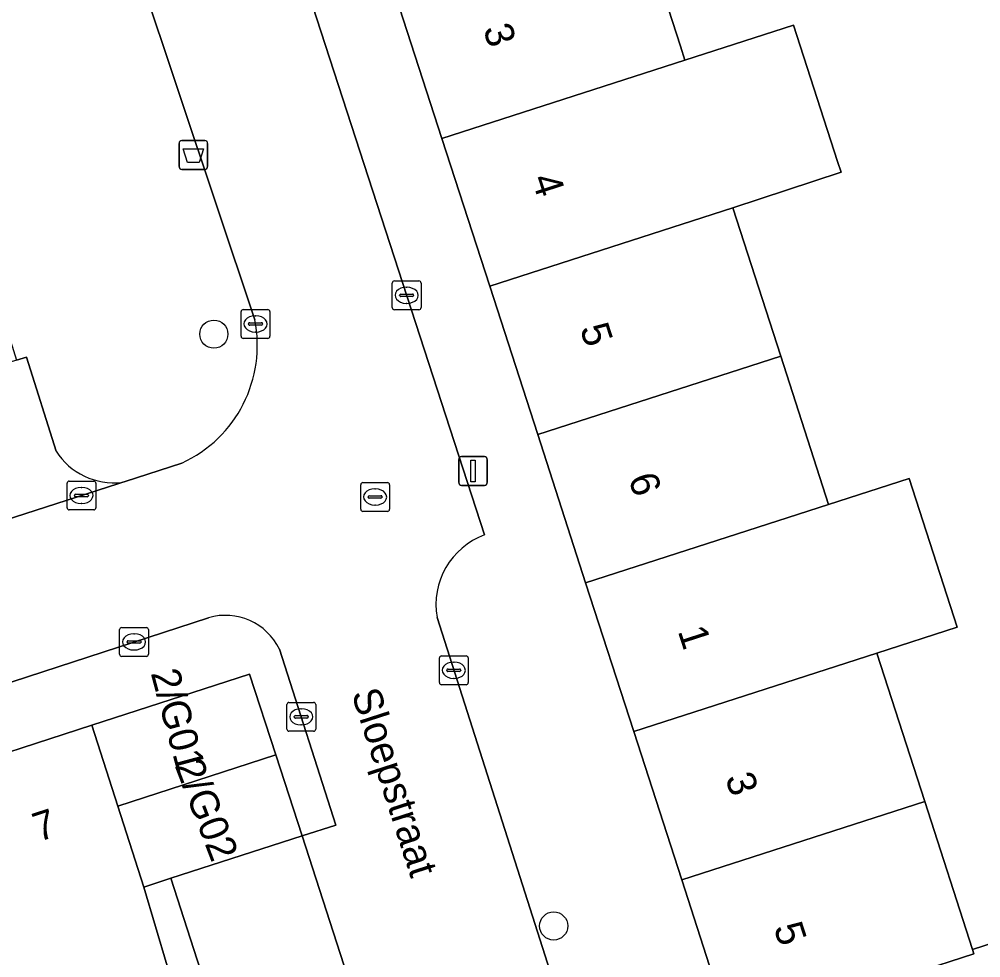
# Model space of a CAD drawing. Extents: x 159371 to 159986, y 382987 to 383597.
# Drawn here: x 159572.4 to 159605.74, y 383099.38 to 383131.92 of the extents above; entities that cross this region are included whole.
import ezdxf

# ---------------------------------------------------------------- set-up
doc = ezdxf.new("R2010")
doc.units = 0
for name, color, linetype in [('IMGEO_Afvalbak', 7, 'Continuous'), ('IMGEO_Boom', 7, 'Continuous'), ('IMGEO_Erf', 7, 'Continuous'), ('IMGEO_Groenvoorziening', 7, 'Continuous'), ('IMGEO_Kolk', 7, 'Continuous'), ('IMGEO_Lichtmast', 7, 'Continuous'), ('IMGEO_Openbare_ruimte_label', 7, 'Continuous'), ('IMGEO_Pand', 7, 'Continuous'), ('IMGEO_Pand_nummerreeks', 7, 'Continuous'), ('IMGEO_Parkeervlak_open', 7, 'Continuous'), ('IMGEO_Rijbaan_lokaal_open', 7, 'Continuous'), ('IMGEO_Rioolput', 7, 'Continuous'), ('IMGEO_Voetpad_open', 7, 'Continuous')]:
    doc.layers.add(name, color=color, linetype=linetype)

msp = doc.modelspace()

# ---------------------------------------------------------------- linework, layer by layer
at = {"layer": 'IMGEO_Afvalbak'}
for p, q in [((159577.943, 383126.815), (159577.943, 383127.615)), ((159577.943, 383127.615), (159577.943, 383126.815)), ((159578.043, 383127.715), (159578.833, 383127.715)), ((159578.833, 383127.715), (159578.043, 383127.715)), ((159578.933, 383127.615), (159578.933, 383126.815)), ((159578.933, 383126.815), (159578.933, 383127.615)), ((159578.833, 383126.715), (159578.043, 383126.715)), ((159578.043, 383126.715), (159578.833, 383126.715))]:
    msp.add_line(p, q, dxfattribs=at)
msp.add_lwpolyline([(159578.086, 383127.429), (159578.79, 383127.429), (159578.641, 383126.959), (159578.235, 383126.959), (159578.086, 383127.429)], dxfattribs=at)
for centre, start, end in [((159578.043, 383127.615), 90, 180), ((159578.043, 383127.615), 90, 180), ((159578.833, 383127.615), 0, 90), ((159578.833, 383127.615), 360, 90), ((159578.043, 383126.815), 180, 270), ((159578.043, 383126.815), 180, 270), ((159578.833, 383126.815), 270, 0), ((159578.833, 383126.815), 270, 0)]:
    msp.add_arc(centre, 0.1, start, end, dxfattribs=at)
at = {"layer": 'IMGEO_Boom'}
for centre in [(159579.15, 383121.002), (159590.933, 383100.481)]:
    msp.add_circle(centre, 0.489, dxfattribs=at)
at = {"layer": 'IMGEO_Erf'}
msp.add_lwpolyline([(159593.791, 383135.74), (159595.329, 383130.983), (159595.484, 383130.504), (159599.251, 383131.718), (159600.775, 383126.99), (159600.896, 383126.615), (159597.141, 383125.381), (159598.804, 383120.238), (159600.467, 383115.094), (159603.258, 383115.994), (159604.92, 383110.841), (159602.134, 383109.942), (159603.797, 383104.799), (159605.459, 383099.66), (159616.414, 383103.202)], dxfattribs=at)
at = {"layer": 'IMGEO_Groenvoorziening'}
for points in [[(159568.059, 383133.514), (159569.251, 383129.752), (159571.294, 383123.299), (159571.459, 383122.778), (159572.307, 383120.099), (159572.649, 383120.207), (159573.679, 383116.948)], [(159580.568, 383121.503), (159576.594, 383133.402)], [(159575.96, 383115.86), (159576.075, 383115.897), (159578.043, 383116.532)]]:
    msp.add_lwpolyline(points, dxfattribs=at)
for centre, radius, start, end in [((159576.16, 383120.615), 4.497, 294.7577, 11.386), ((159575.69, 383118.23), 2.385, 212.5102, 276.489)]:
    msp.add_arc(centre, radius, start, end, dxfattribs=at)
at = {"layer": 'IMGEO_Kolk'}
for p, q in [((159585.334, 383121.923), (159585.334, 383122.775)), ((159585.409, 383122.849), (159586.261, 383122.849)), ((159585.822, 383122.629), (159585.847, 383122.629)), ((159586.335, 383122.775), (159586.335, 383121.923)), ((159585.593, 383122.343), (159585.593, 383122.355)), ((159586.031, 383122.306), (159585.633, 383122.306)), ((159585.636, 383122.392), (159586.034, 383122.392)), ((159586.077, 383122.355), (159586.077, 383122.343)), ((159585.845, 383122.069), (159585.82, 383122.069)), ((159580.093, 383120.93), (159580.093, 383121.782)), ((159580.168, 383121.856), (159581.02, 383121.856)), ((159580.581, 383121.636), (159580.606, 383121.636)), ((159581.094, 383121.782), (159581.094, 383120.93)), ((159586.261, 383121.849), (159585.409, 383121.849)), ((159580.352, 383121.35), (159580.352, 383121.362)), ((159580.79, 383121.313), (159580.392, 383121.313)), ((159580.395, 383121.399), (159580.793, 383121.399)), ((159580.836, 383121.362), (159580.836, 383121.35)), ((159580.604, 383121.076), (159580.579, 383121.076)), ((159581.02, 383120.856), (159580.168, 383120.856)), ((159574.134, 383115.907), (159574.986, 383115.907)), ((159574.059, 383114.981), (159574.059, 383115.833)), ((159574.547, 383115.687), (159574.572, 383115.687)), ((159575.06, 383115.833), (159575.06, 383114.981)), ((159574.318, 383115.401), (159574.318, 383115.413)), ((159574.756, 383115.364), (159574.358, 383115.364)), ((159574.361, 383115.45), (159574.759, 383115.45)), ((159574.802, 383115.413), (159574.802, 383115.401)), ((159574.986, 383114.907), (159574.134, 383114.907)), ((159574.57, 383115.127), (159574.545, 383115.127)), ((159575.883, 383109.904), (159575.883, 383110.756)), ((159575.958, 383110.83), (159576.81, 383110.83)), ((159576.371, 383110.61), (159576.396, 383110.61)), ((159576.884, 383110.756), (159576.884, 383109.904)), ((159576.142, 383110.324), (159576.142, 383110.336)), ((159576.58, 383110.287), (159576.182, 383110.287)), ((159576.185, 383110.373), (159576.583, 383110.373)), ((159576.626, 383110.336), (159576.626, 383110.324)), ((159576.394, 383110.05), (159576.369, 383110.05)), ((159576.81, 383109.83), (159575.958, 383109.83)), ((159586.969, 383108.921), (159586.969, 383109.773)), ((159587.044, 383109.847), (159587.896, 383109.847)), ((159587.457, 383109.627), (159587.482, 383109.627)), ((159587.97, 383109.773), (159587.97, 383108.921)), ((159587.228, 383109.341), (159587.228, 383109.353)), ((159587.666, 383109.304), (159587.268, 383109.304)), ((159587.271, 383109.39), (159587.669, 383109.39)), ((159587.712, 383109.353), (159587.712, 383109.341)), ((159587.48, 383109.067), (159587.455, 383109.067)), ((159587.896, 383108.847), (159587.044, 383108.847)), ((159581.755, 383108.233), (159582.607, 383108.233)), ((159581.68, 383107.307), (159581.68, 383108.159)), ((159582.168, 383108.013), (159582.193, 383108.013)), ((159582.681, 383108.159), (159582.681, 383107.307)), ((159581.939, 383107.727), (159581.939, 383107.739)), ((159582.377, 383107.69), (159581.979, 383107.69)), ((159581.982, 383107.776), (159582.38, 383107.776)), ((159582.423, 383107.739), (159582.423, 383107.727)), ((159582.607, 383107.233), (159581.755, 383107.233)), ((159582.191, 383107.453), (159582.166, 383107.453))]:
    msp.add_line(p, q, dxfattribs=at)
for points in [[(159585.334, 383121.923), (159585.334, 383122.775)], [(159585.409, 383122.849), (159586.261, 383122.849)], [(159586.335, 383122.775), (159586.335, 383121.923)], [(159580.093, 383120.93), (159580.093, 383121.782)], [(159580.168, 383121.856), (159581.02, 383121.856)], [(159581.094, 383121.782), (159581.094, 383120.93)], [(159586.261, 383121.849), (159585.409, 383121.849)], [(159581.02, 383120.856), (159580.168, 383120.856)], [(159574.134, 383115.907), (159574.986, 383115.907)], [(159574.059, 383114.981), (159574.059, 383115.833)], [(159575.06, 383115.833), (159575.06, 383114.981)], [(159574.986, 383114.907), (159574.134, 383114.907)], [(159575.883, 383109.904), (159575.883, 383110.756)], [(159575.958, 383110.83), (159576.81, 383110.83)], [(159576.884, 383110.756), (159576.884, 383109.904)], [(159576.81, 383109.83), (159575.958, 383109.83)], [(159586.969, 383108.921), (159586.969, 383109.773)], [(159587.044, 383109.847), (159587.896, 383109.847)], [(159587.97, 383109.773), (159587.97, 383108.921)], [(159587.896, 383108.847), (159587.044, 383108.847)], [(159581.755, 383108.233), (159582.607, 383108.233)], [(159581.68, 383107.307), (159581.68, 383108.159)], [(159582.681, 383108.159), (159582.681, 383107.307)], [(159582.607, 383107.233), (159581.755, 383107.233)]]:
    msp.add_lwpolyline(points, dxfattribs=at)
for centre, radius, start, end in [((159585.411, 383122.773), 0.0765, 91.552, 178.448), ((159585.411, 383122.773), 0.0765, 91.552, 178.448), ((159586.259, 383122.773), 0.0765, 1.552, 88.448), ((159586.259, 383122.773), 0.0765, 1.552, 88.448), ((159585.633, 383122.352), 0.0403, 85.8775, 175.7526), ((159585.63, 383122.342), 0.0366, 178.938, 274.7102), ((159586.034, 383122.349), 0.043, 264.8664, 352.4533), ((159586.038, 383122.354), 0.0386, 1.7309, 96.639), ((159585.411, 383121.925), 0.0765, 181.552, 268.448), ((159585.411, 383121.925), 0.0765, 181.552, 268.448), ((159586.259, 383121.925), 0.0765, 271.552, 358.448), ((159586.259, 383121.925), 0.0765, 271.552, 358.448), ((159580.17, 383121.78), 0.0765, 91.552, 178.448), ((159580.17, 383121.78), 0.0765, 91.552, 178.448), ((159581.018, 383121.78), 0.0765, 1.552, 88.448), ((159581.018, 383121.78), 0.0765, 1.552, 88.448), ((159580.392, 383121.359), 0.0403, 85.8775, 175.7526), ((159580.389, 383121.349), 0.0366, 178.938, 274.7102), ((159580.793, 383121.356), 0.043, 264.8664, 352.4533), ((159580.797, 383121.361), 0.0386, 1.7309, 96.639), ((159580.17, 383120.932), 0.0765, 181.552, 268.448), ((159580.17, 383120.932), 0.0765, 181.552, 268.448), ((159581.018, 383120.932), 0.0765, 271.552, 358.448), ((159581.018, 383120.932), 0.0765, 271.552, 358.448), ((159574.136, 383115.831), 0.0765, 91.552, 178.448), ((159574.136, 383115.831), 0.0765, 91.552, 178.448), ((159574.984, 383115.831), 0.0765, 1.552, 88.448), ((159574.984, 383115.831), 0.0765, 1.552, 88.448), ((159574.358, 383115.41), 0.0403, 85.8775, 175.7526), ((159574.355, 383115.4), 0.0366, 178.938, 274.7102), ((159574.759, 383115.407), 0.043, 264.8664, 352.4533), ((159574.763, 383115.412), 0.0386, 1.7309, 96.639), ((159574.136, 383114.983), 0.0765, 181.552, 268.448), ((159574.136, 383114.983), 0.0765, 181.552, 268.448), ((159574.984, 383114.983), 0.0765, 271.552, 358.448), ((159574.984, 383114.983), 0.0765, 271.552, 358.448), ((159575.96, 383110.754), 0.0765, 91.552, 178.448), ((159575.96, 383110.754), 0.0765, 91.552, 178.448), ((159576.808, 383110.754), 0.0765, 1.552, 88.448), ((159576.808, 383110.754), 0.0765, 1.552, 88.448), ((159576.182, 383110.333), 0.0403, 85.8775, 175.7526), ((159576.179, 383110.323), 0.0366, 178.938, 274.7102), ((159576.583, 383110.33), 0.043, 264.8664, 352.4533), ((159576.587, 383110.335), 0.0386, 1.7309, 96.639), ((159575.96, 383109.906), 0.0765, 181.552, 268.448), ((159575.96, 383109.906), 0.0765, 181.552, 268.448), ((159576.808, 383109.906), 0.0765, 271.552, 358.448), ((159576.808, 383109.906), 0.0765, 271.552, 358.448), ((159587.046, 383109.771), 0.0765, 91.552, 178.448), ((159587.046, 383109.771), 0.0765, 91.552, 178.448), ((159587.894, 383109.771), 0.0765, 1.552, 88.448), ((159587.894, 383109.771), 0.0765, 1.552, 88.448), ((159587.268, 383109.35), 0.0403, 85.8775, 175.7526), ((159587.265, 383109.34), 0.0366, 178.938, 274.7102), ((159587.669, 383109.347), 0.043, 264.8664, 352.4533), ((159587.673, 383109.352), 0.0386, 1.7309, 96.639), ((159587.046, 383108.923), 0.0765, 181.552, 268.448), ((159587.046, 383108.923), 0.0765, 181.552, 268.448), ((159587.894, 383108.923), 0.0765, 271.552, 358.448), ((159587.894, 383108.923), 0.0765, 271.552, 358.448), ((159581.757, 383108.157), 0.0765, 91.552, 178.448), ((159581.757, 383108.157), 0.0765, 91.552, 178.448), ((159582.605, 383108.157), 0.0765, 1.552, 88.448), ((159582.605, 383108.157), 0.0765, 1.552, 88.448), ((159581.979, 383107.736), 0.0403, 85.8775, 175.7526), ((159581.976, 383107.726), 0.0366, 178.938, 274.7102), ((159582.38, 383107.733), 0.043, 264.8664, 352.4533), ((159582.384, 383107.738), 0.0386, 1.7309, 96.639), ((159581.757, 383107.309), 0.0765, 181.552, 268.448), ((159581.757, 383107.309), 0.0765, 181.552, 268.448), ((159582.605, 383107.309), 0.0765, 271.552, 358.448), ((159582.605, 383107.309), 0.0765, 271.552, 358.448)]:
    msp.add_arc(centre, radius, start, end, dxfattribs=at)
for centre, major_axis, ratio, start_param, end_param in [((159585.821, 383122.349), (-0.387, 0.002), 0.722429, 4.712389, 7.853982), ((159585.846, 383122.349), (-0.39, 0.002), 0.717154, 1.570796, 4.712389), ((159580.58, 383121.356), (-0.387, 0.002), 0.722429, 4.712389, 7.853982), ((159580.605, 383121.356), (-0.39, 0.002), 0.717154, 1.570796, 4.712389), ((159574.546, 383115.407), (-0.387, 0.002), 0.722429, 4.712389, 7.853982), ((159574.571, 383115.407), (-0.39, 0.002), 0.717154, 1.570796, 4.712389), ((159576.37, 383110.33), (-0.387, 0.002), 0.722429, 4.712389, 7.853982), ((159576.395, 383110.33), (-0.39, 0.002), 0.717154, 1.570796, 4.712389), ((159587.456, 383109.347), (-0.387, 0.002), 0.722429, 4.712389, 7.853982), ((159587.481, 383109.347), (-0.39, 0.002), 0.717154, 1.570796, 4.712389), ((159582.167, 383107.733), (-0.387, 0.002), 0.722429, 4.712389, 7.853982), ((159582.192, 383107.733), (-0.39, 0.002), 0.717154, 1.570796, 4.712389)]:
    msp.add_ellipse(centre, major_axis=major_axis, ratio=ratio, start_param=start_param, end_param=end_param, dxfattribs=at)
at = {"layer": 'IMGEO_Lichtmast'}
for p, q in [((159587.642, 383115.857), (159587.642, 383116.657)), ((159587.642, 383116.657), (159587.642, 383115.857)), ((159587.742, 383116.757), (159588.532, 383116.757)), ((159588.532, 383116.757), (159587.742, 383116.757)), ((159588.632, 383116.657), (159588.632, 383115.857)), ((159588.632, 383115.857), (159588.632, 383116.657)), ((159588.532, 383115.757), (159587.742, 383115.757)), ((159587.742, 383115.757), (159588.532, 383115.757))]:
    msp.add_line(p, q, dxfattribs=at)
msp.add_lwpolyline([(159588.062, 383116.632), (159588.212, 383116.632), (159588.212, 383115.882), (159588.062, 383115.882), (159588.062, 383116.632)], dxfattribs=at)
for centre, start, end in [((159587.742, 383116.657), 90, 180), ((159587.742, 383116.657), 90, 180), ((159588.532, 383116.657), 0, 90), ((159588.532, 383116.657), 360, 90), ((159587.742, 383115.857), 180, 270), ((159587.742, 383115.857), 180, 270), ((159588.532, 383115.857), 270, 0), ((159588.532, 383115.857), 270, 0)]:
    msp.add_arc(centre, 0.1, start, end, dxfattribs=at)
at = {"layer": 'IMGEO_Pand'}
for points in [[(159585.325, 383133.147), (159587.058, 383127.787), (159595.484, 383130.504), (159595.329, 383130.983), (159593.791, 383135.74), (159591.018, 383134.843), (159590.977, 383134.971), (159588.151, 383134.059)], [(159595.484, 383130.504), (159587.058, 383127.787), (159588.716, 383122.663), (159597.141, 383125.381), (159600.896, 383126.615), (159600.775, 383126.99), (159599.251, 383131.718)], [(159590.379, 383117.52), (159598.804, 383120.238), (159597.141, 383125.381), (159588.716, 383122.663)], [(159600.467, 383115.094), (159598.804, 383120.238), (159590.379, 383117.52), (159592.042, 383112.377)], [(159600.467, 383115.094), (159592.042, 383112.377), (159593.709, 383107.224), (159602.134, 383109.942), (159604.92, 383110.841), (159603.258, 383115.994)], [(159593.709, 383107.224), (159595.372, 383102.081), (159603.797, 383104.799), (159602.134, 383109.942)], [(159581.3, 383106.414), (159580.39, 383109.217), (159574.918, 383107.441), (159575.821, 383104.635)], [(159569.577, 383105.707), (159572.256, 383097.384), (159572.778, 383097.554), (159577.533, 383099.097), (159576.724, 383101.831), (159575.821, 383104.635), (159574.918, 383107.441)], [(159581.3, 383106.414), (159575.821, 383104.635), (159576.724, 383101.831), (159577.654, 383102.133), (159582.21, 383103.611)], [(159603.797, 383104.799), (159595.372, 383102.081), (159597.081, 383096.796), (159598.673, 383097.311), (159603.431, 383098.849), (159605.504, 383099.52), (159605.459, 383099.66)]]:
    msp.add_lwpolyline(points, close=True, dxfattribs=at)
at = {"layer": 'IMGEO_Parkeervlak_open'}
for points in [[(159573.679, 383116.948), (159572.649, 383120.207), (159572.307, 383120.099), (159555.969, 383114.93), (159552.156, 383113.724), (159552.25, 383113.426), (159553.057, 383110.875)], [(159551.592, 383107.999), (159575.853, 383115.826)], [(159575.853, 383115.826), (159575.96, 383115.86)]]:
    msp.add_lwpolyline(points, dxfattribs=at)
msp.add_lwpolyline([(159577.654, 383102.133), (159584.26, 383081.67), (159588.82, 383083.137), (159582.21, 383103.611)], close=True, dxfattribs=at)
msp.add_arc((159575.69, 383118.23), 2.385, 212.5102, 276.489, dxfattribs=at)
at = {"layer": 'IMGEO_Rijbaan_lokaal_open'}
for points in [[(159588.536, 383114.043), (159581.226, 383136.531)], [(159576.594, 383133.402), (159580.568, 383121.503)], [(159578.043, 383116.532), (159576.075, 383115.897), (159575.96, 383115.86), (159575.853, 383115.826), (159551.592, 383107.999), (159553.35, 383102.825), (159578.967, 383111.171)], [(159581.43, 383110.08), (159583.382, 383103.973), (159582.21, 383103.611), (159588.82, 383083.137), (159595.214, 383085.195), (159592.367, 383094.013), (159586.889, 383111.175)]]:
    msp.add_lwpolyline(points, dxfattribs=at)
for centre, radius, start, end in [((159576.16, 383120.615), 4.497, 294.7577, 11.386), ((159589.441, 383111.616), 2.59, 110.4514, 189.8139), ((159579.545, 383109.15), 2.102, 26.2595, 105.9581)]:
    msp.add_arc(centre, radius, start, end, dxfattribs=at)
at = {"layer": 'IMGEO_Rioolput'}
for p, q in [((159584.241, 383114.93), (159584.241, 383115.782)), ((159584.316, 383115.856), (159585.168, 383115.856)), ((159584.729, 383115.636), (159584.754, 383115.636)), ((159585.242, 383115.782), (159585.242, 383114.93)), ((159584.5, 383115.35), (159584.5, 383115.362)), ((159584.938, 383115.313), (159584.54, 383115.313)), ((159584.543, 383115.399), (159584.941, 383115.399)), ((159584.984, 383115.362), (159584.984, 383115.35)), ((159584.752, 383115.076), (159584.727, 383115.076)), ((159585.168, 383114.856), (159584.316, 383114.856))]:
    msp.add_line(p, q, dxfattribs=at)
for points in [[(159584.241, 383114.93), (159584.241, 383115.782)], [(159584.316, 383115.856), (159585.168, 383115.856)], [(159585.242, 383115.782), (159585.242, 383114.93)], [(159585.168, 383114.856), (159584.316, 383114.856)]]:
    msp.add_lwpolyline(points, dxfattribs=at)
for centre, radius, start, end in [((159584.318, 383115.78), 0.0765, 91.552, 178.448), ((159584.318, 383115.78), 0.0765, 91.552, 178.448), ((159585.166, 383115.78), 0.0765, 1.552, 88.448), ((159585.166, 383115.78), 0.0765, 1.552, 88.448), ((159584.54, 383115.359), 0.0403, 85.8775, 175.7526), ((159584.537, 383115.349), 0.0366, 178.938, 274.7102), ((159584.941, 383115.356), 0.043, 264.8664, 352.4533), ((159584.945, 383115.361), 0.0386, 1.7309, 96.639), ((159584.318, 383114.932), 0.0765, 181.552, 268.448), ((159584.318, 383114.932), 0.0765, 181.552, 268.448), ((159585.166, 383114.932), 0.0765, 271.552, 358.448), ((159585.166, 383114.932), 0.0765, 271.552, 358.448)]:
    msp.add_arc(centre, radius, start, end, dxfattribs=at)
for centre, major_axis, ratio, start_param, end_param in [((159584.728, 383115.356), (-0.387, 0.002), 0.722429, 4.712389, 7.853982), ((159584.753, 383115.356), (-0.39, 0.002), 0.717154, 1.570796, 4.712389)]:
    msp.add_ellipse(centre, major_axis=major_axis, ratio=ratio, start_param=start_param, end_param=end_param, dxfattribs=at)
at = {"layer": 'IMGEO_Voetpad_open'}
for points in [[(159593.709, 383107.224), (159592.042, 383112.377), (159590.379, 383117.52), (159588.716, 383122.663), (159587.058, 383127.787), (159585.325, 383133.147), (159583.552, 383138.629), (159581.414, 383138.511)], [(159581.18, 383136.688), (159581.226, 383136.531), (159588.536, 383114.043)], [(159578.967, 383111.171), (159553.35, 383102.825), (159550.697, 383101.96), (159526.127, 383093.955), (159526.812, 383091.837), (159528.151, 383092.259), (159533.546, 383094.01), (159538.679, 383095.677), (159543.819, 383097.345), (159549.045, 383099.042), (159554.184, 383100.71), (159559.316, 383102.376), (159564.446, 383104.041), (159569.577, 383105.707), (159574.918, 383107.441), (159580.39, 383109.217), (159581.3, 383106.414), (159582.21, 383103.611), (159583.382, 383103.973), (159581.43, 383110.08)], [(159586.889, 383111.175), (159592.367, 383094.013)], [(159597.081, 383096.796), (159595.372, 383102.081), (159593.709, 383107.224)], [(159616.414, 383103.202), (159605.459, 383099.66), (159605.504, 383099.52), (159603.431, 383098.849), (159598.673, 383097.311), (159599.16, 383095.895), (159611.878, 383100.008)], [(159584.26, 383081.67), (159577.654, 383102.133), (159576.724, 383101.831), (159577.533, 383099.097)]]:
    msp.add_lwpolyline(points, dxfattribs=at)
for centre, radius, start, end in [((159589.441, 383111.616), 2.59, 110.4514, 189.8139), ((159579.545, 383109.15), 2.102, 26.2595, 105.9581)]:
    msp.add_arc(centre, radius, start, end, dxfattribs=at)

# ---------------------------------------------------------------- texts
at = {"layer": 'IMGEO_Openbare_ruimte_label'}
msp.add_text('Sloepstraat', height=1, rotation=287.8734, dxfattribs=at).set_placement((159583.913, 383108.543))
at = {"layer": 'IMGEO_Pand_nummerreeks'}
for s, rotation, p in [('3', 287.9212, (159588.477, 383131.588)), ('4', 287.9219, (159590.157, 383126.396)), ('5', 287.9212, (159591.835, 383121.203)), ('6', 287.9212, (159593.515, 383116.011)), ('1', 287.9219, (159595.23, 383110.709)), ('2/G01', 285.0685, (159576.957, 383109.253)), ('2/G02', 291.0375, (159577.784, 383106.046)), ('3', 287.9215, (159596.874, 383105.624)), ('7', 17.985, (159573.07, 383103.392)), ('5', 287.9219, (159598.554, 383100.43))]:
    msp.add_text(s, height=1, rotation=rotation, dxfattribs=at).set_placement(p)

doc.saveas('drawing.dxf')
